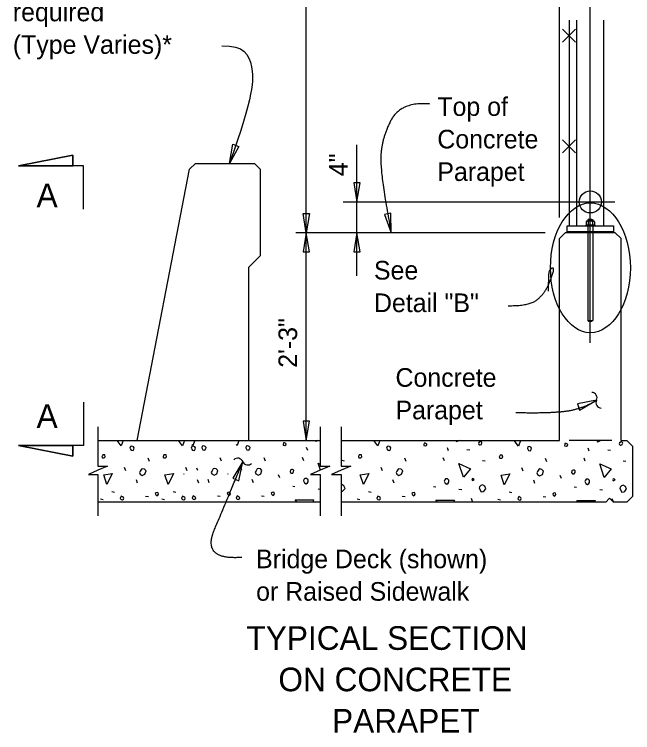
# Model space of a CAD drawing. Extents: x 0.2 to 40.8, y 0.5 to 25.7.
# Drawn here: x 33.82 to 40.51, y 11.06 to 18.84 of the extents above; entities that cross this region are included whole.
import ezdxf

# ---------------------------------------------------------------- set-up
doc = ezdxf.new("R2010")
doc.units = 0
for name, color, linetype in [('CL_Major', 7, 'Continuous'), ('Dimension', 7, 'Continuous'), ('Miscellaneous', 7, 'Continuous'), ('SteelMisc', 7, 'Continuous'), ('SteelMisc_h', 7, 'Continuous'), ('SupstrConc', 7, 'Continuous'), ('SupstrConc_h', 7, 'Continuous'), ('TextStructures', 7, 'Continuous')]:
    doc.layers.add(name, color=color, linetype=linetype)

# ---------------------------------------------------------------- blocks, each defined once
blk = doc.blocks.new('Terminator-Arrow')
at = {"layer": 'Dimension'}
blk.add_lwpolyline([(0, 0), (-0.00041, 0.000069), (-0.00041, -0.000069), (0, 0)], dxfattribs=at)
blk.add_lwpolyline([(0, 0), (-0.00041, 0.000069), (-0.00041, -0.000069)], close=True, dxfattribs=at)

msp = doc.modelspace()

# ---------------------------------------------------------------- linework, layer by layer
at = {"layer": 'CL_Major'}
for p, q in [((40.0537, 15.2829), (40.0537, 19.5023)), ((37.3776, 16.8078), (40.3194, 16.8078))]:
    msp.add_line(p, q, dxfattribs=at)
at = {"layer": 'Dimension'}
for p, q in [((36.9797, 14.2246), (36.9797, 22.8079)), ((39.7204, 16.6402), (39.7204, 19.0859)), ((37.5276, 16.0092), (37.5276, 17.4261)), ((33.8643, 17.1974), (34.4503, 17.3146)), ((34.4503, 17.3146), (34.4503, 17.1974)), ((34.5675, 17.1974), (33.8643, 17.1974)), ((34.5675, 16.7286), (34.5675, 17.1974)), ((40.0537, 16.5552), (40.0537, 16.5545)), ((39.5643, 16.4746), (36.8659, 16.4746)), ((34.5675, 14.6399), (34.5675, 14.1711)), ((34.5675, 14.1711), (33.8643, 14.1711)), ((33.8643, 14.1711), (34.4503, 14.0539)), ((34.4503, 14.0539), (34.4503, 14.1711))]:
    msp.add_line(p, q, dxfattribs=at)
for points in [[(34.4503, 17.1974), (34.4503, 17.3146), (33.8643, 17.1974)], [(37.5276, 16.8079), (37.5629, 17.0161), (37.4923, 17.0161)], [(36.9797, 16.4746), (36.9444, 16.6828), (37.015, 16.6828)], [(37.8983, 16.4746), (37.8958, 16.6858), (37.8263, 16.6731)], [(36.9797, 16.4746), (36.9444, 16.2663), (37.015, 16.2663)], [(37.5276, 16.4746), (37.4923, 16.2663), (37.5629, 16.2663)], [(40.1214, 14.6607), (39.9139, 14.6211), (39.9386, 14.5549)], [(36.9797, 14.2246), (37.015, 14.4328), (36.9444, 14.4328)], [(34.4503, 14.1711), (34.4503, 14.0539), (33.8643, 14.1711)], [(36.2916, 13.9969), (36.1831, 13.8157), (36.2488, 13.79)]]:
    msp.add_lwpolyline(points, close=True, dxfattribs=at)
for points in [[(34.7238, 14.3746), (34.7238, 13.9474), (34.8272, 13.9474), (34.7238, 13.9024), (34.6205, 13.8574), (34.7238, 13.8574), (34.7238, 13.4079)], [(37.1296, 14.3746), (37.1296, 13.9474), (37.233, 13.9474), (37.1296, 13.9024), (37.0263, 13.8574), (37.1296, 13.8574), (37.1296, 13.4079)], [(37.3569, 14.3746), (37.3569, 13.9474), (37.4602, 13.9474), (37.3569, 13.9024), (37.2536, 13.8574), (37.3569, 13.8574), (37.3569, 13.4079)]]:
    msp.add_lwpolyline(points, dxfattribs=at)
for centre, start, end in [((40.0672, 14.6869), 334.61622, 86.34344), ((40.1749, 14.6358), 154.61622, 266.34344), ((36.236, 13.9739), 22.88008, 134.6073), ((36.3458, 14.0202), 202.88008, 314.6073)]:
    msp.add_arc(centre, 0.0596, start, end, dxfattribs=at)
msp.add_ellipse((40.055, 16.0943), major_axis=(0, 0.7024), ratio=0.61552, dxfattribs=at)
for points, degree in [([(36.0647, 18.496), (36.3065, 18.5019), (36.4127, 18.3129), (36.4127, 17.9586), (36.1473, 17.2245)], 3), ([(38.3183, 17.8669), (38.0045, 17.8975), (37.7862, 17.4818), (37.7862, 17.0625), (37.8983, 16.4745)], 2), ([(39.1649, 15.6846), (39.3915, 15.6806), (39.562, 15.8155), (39.6571, 16.0457), (39.6571, 16.0974), (39.6199, 16.0825), (39.5976, 16.0298), (39.599, 15.843)], 2), ([(39.246, 14.5284), (39.5846, 14.5201), (39.9562, 14.5615), (40.1214, 14.6607)], 2), ([(36.2826, 12.9596), (36.0506, 12.9429), (35.9147, 13.1019), (36.0652, 13.445), (36.2916, 13.9969)], 2)]:
    msp.add_open_spline(points, degree=degree, dxfattribs=at)
at = {"layer": 'Miscellaneous'}
for p, q in [((39.8952, 18.6785), (39.7538, 18.5373)), ((39.7538, 18.6785), (39.8952, 18.5373)), ((39.8952, 17.4785), (39.7538, 17.3373)), ((39.7538, 17.4785), (39.8952, 17.3373)), ((40.0425, 16.6169), (40.0633, 16.6169)), ((40.0425, 16.6072), (40.0633, 16.6072)), ((39.8037, 16.4815), (40.3037, 16.4815)), ((39.8037, 16.478), (40.3037, 16.478)), ((35.3909, 14.2246), (35.3923, 14.2243)), ((38.169, 14.2246), (38.1703, 14.2243)), ((39.6751, 14.2246), (39.6941, 14.2207)), ((36.9947, 14.1164), (36.9824, 14.15)), ((38.5186, 14.1129), (38.5062, 14.1465)), ((38.7183, 14.1288), (38.7501, 14.1253)), ((40.0424, 14.1094), (40.03, 14.143)), ((40.2421, 14.1253), (40.274, 14.1218)), ((35.2827, 13.998), (35.2685, 14.0334)), ((36.0602, 14.0015), (36.0461, 14.0369)), ((36.5369, 14.0015), (36.5228, 14.0369)), ((36.9523, 14.0068), (36.9382, 14.0422)), ((37.3624, 14.0139), (37.3907, 14.0068)), ((38.0607, 13.998), (38.0466, 14.0334)), ((38.4761, 14.0033), (38.462, 14.0387)), ((38.8863, 14.0104), (38.9145, 14.0033)), ((39.5845, 13.9945), (39.5704, 14.0298)), ((39.9999, 13.9998), (39.9858, 14.0351)), ((40.4101, 14.0068), (40.4384, 13.9998)), ((35.0263, 13.8972), (35.0122, 13.9326)), ((35.6898, 13.8972), (35.6757, 13.9326)), ((35.8039, 13.9008), (35.7944, 13.9245)), ((36.2806, 13.9008), (36.2711, 13.9245)), ((37.8044, 13.8972), (37.7902, 13.9326)), ((39.3282, 13.8937), (39.3141, 13.9291)), ((36.6942, 13.8195), (36.6801, 13.8548)), ((39.7419, 13.8124), (39.7277, 13.8477)), ((35.1519, 13.7647), (35.1395, 13.7983)), ((35.8154, 13.7647), (35.803, 13.7983)), ((35.9294, 13.7682), (35.917, 13.8018)), ((36.4061, 13.7682), (36.3937, 13.8018)), ((37.9299, 13.7647), (37.9175, 13.7983)), ((39.4537, 13.7611), (39.4413, 13.7947)), ((36.8321, 13.7311), (36.8569, 13.7275)), ((37.1079, 13.7028), (37.1296, 13.699)), ((38.3559, 13.7275), (38.3807, 13.724)), ((38.6317, 13.6993), (38.6617, 13.694)), ((39.8797, 13.724), (39.9045, 13.7205)), ((40.1555, 13.6957), (40.1856, 13.6904)), ((34.8743, 13.6745), (34.9026, 13.6674)), ((35.2402, 13.6232), (35.2703, 13.6179)), ((35.5378, 13.6745), (35.5661, 13.6674)), ((36.0178, 13.6268), (36.0478, 13.6215)), ((36.4945, 13.6268), (36.5245, 13.6215)), ((37.6524, 13.6745), (37.6806, 13.6674)), ((38.0183, 13.6232), (38.0483, 13.6179)), ((39.1762, 13.671), (39.2045, 13.6639)), ((39.5421, 13.6197), (39.5721, 13.6144)), ((34.7523, 13.595), (34.7806, 13.5879)), ((35.4158, 13.595), (35.4441, 13.5879)), ((37.5304, 13.595), (37.5587, 13.5879)), ((38.7802, 13.5649), (38.7678, 13.5985)), ((39.0542, 13.5914), (39.0825, 13.5844)), ((40.304, 13.5614), (40.2916, 13.595))]:
    msp.add_line(p, q, dxfattribs=at)
for points in [[(39.8246, 18.7753), (39.8246, 16.5475)], [(34.9751, 14.1677), (34.9319, 14.2246)], [(34.9963, 14.2246), (34.9751, 14.1677)], [(35.0741, 14.1359), (35.0829, 14.12), (35.1041, 14.1164), (35.113, 14.1324), (35.1165, 14.1465), (35.1077, 14.1553), (35.0918, 14.1642), (35.0758, 14.1589), (35.0705, 14.143), (35.0741, 14.1359)], [(35.6386, 14.1677), (35.5954, 14.2246)], [(35.6598, 14.2246), (35.6386, 14.1677)], [(35.7376, 14.1359), (35.7464, 14.12), (35.7676, 14.1164), (35.7765, 14.1324), (35.78, 14.1465), (35.7712, 14.1553), (35.7553, 14.1642), (35.7393, 14.1589), (35.734, 14.143), (35.7376, 14.1359)], [(35.7526, 14.1713), (35.7438, 14.1829)], [(35.7725, 14.2246), (35.7526, 14.1713)], [(35.8516, 14.1394), (35.8605, 14.1235), (35.8817, 14.12), (35.8905, 14.1359), (35.894, 14.15), (35.8852, 14.1589), (35.8693, 14.1677), (35.8534, 14.1624), (35.8481, 14.1465), (35.8516, 14.1394)], [(36.2293, 14.1713), (36.2205, 14.1829)], [(36.2492, 14.2246), (36.2293, 14.1713)], [(36.3283, 14.1394), (36.3371, 14.1235), (36.3584, 14.12), (36.3672, 14.1359), (36.3707, 14.15), (36.3619, 14.1589), (36.346, 14.1677), (36.3301, 14.1624), (36.3248, 14.1465), (36.3283, 14.1394)], [(36.7278, 14.1748), (36.7473, 14.1695), (36.7596, 14.1783), (36.7614, 14.1907), (36.7579, 14.1942), (36.7437, 14.2013), (36.7314, 14.1995), (36.7296, 14.1872), (36.7278, 14.1748)], [(37.0831, 14.2154), (37.0859, 14.2246)], [(37.1034, 14.2246), (37.0831, 14.2154)], [(37.3569, 14.2024), (37.3571, 14.2031), (37.3569, 14.2043)], [(37.7531, 14.1677), (37.7099, 14.2246)], [(37.7744, 14.2246), (37.7531, 14.1677)], [(37.8521, 14.1359), (37.861, 14.12), (37.8822, 14.1164), (37.891, 14.1324), (37.8945, 14.1465), (37.8857, 14.1553), (37.8698, 14.1642), (37.8539, 14.1589), (37.8486, 14.143), (37.8521, 14.1359)], [(38.2516, 14.1713), (38.2711, 14.1659), (38.2834, 14.1748), (38.2852, 14.1872), (38.2817, 14.1907), (38.2675, 14.1978), (38.2552, 14.196), (38.2534, 14.1836), (38.2516, 14.1713)], [(38.6069, 14.2119), (38.6108, 14.2246)], [(38.6351, 14.2246), (38.6069, 14.2119)], [(38.8544, 14.1766), (38.8615, 14.1766), (38.8756, 14.1836), (38.881, 14.1995), (38.8792, 14.2084), (38.865, 14.2154), (38.8474, 14.2048), (38.8438, 14.1942), (38.8474, 14.1836), (38.8544, 14.1766)], [(39.2769, 14.1642), (39.231, 14.2246)], [(39.2995, 14.2246), (39.2769, 14.1642)], [(39.3759, 14.1324), (39.3848, 14.1164), (39.406, 14.1129), (39.4148, 14.1288), (39.4184, 14.143), (39.4095, 14.1518), (39.3936, 14.1606), (39.3777, 14.1553), (39.3724, 14.1394), (39.3759, 14.1324)], [(39.7754, 14.1677), (39.7949, 14.1624), (39.8073, 14.1713), (39.809, 14.1836), (39.8055, 14.1872), (39.7914, 14.1942), (39.779, 14.1925), (39.7772, 14.1801), (39.7754, 14.1677)], [(40.1308, 14.2084), (40.1357, 14.2246)], [(40.1668, 14.2246), (40.1308, 14.2084)], [(40.3782, 14.173), (40.3853, 14.173), (40.3995, 14.1801), (40.4048, 14.196), (40.403, 14.2048), (40.3889, 14.2119), (40.3712, 14.2013), (40.3676, 14.1907), (40.3712, 14.1801), (40.3782, 14.173)], [(34.7718, 14.0387), (34.793, 14.0387), (34.8036, 14.0493), (34.7983, 14.0687), (34.7753, 14.0705), (34.7718, 14.0599), (34.7665, 14.051), (34.7718, 14.0387), (34.7683, 14.0422)], [(35.4353, 14.0387), (35.4565, 14.0387), (35.4671, 14.0493), (35.4618, 14.0687), (35.4388, 14.0705), (35.4353, 14.0599), (35.43, 14.051), (35.4353, 14.0387), (35.4318, 14.0422)], [(37.5498, 14.0387), (37.571, 14.0387), (37.5816, 14.0493), (37.5763, 14.0687), (37.5534, 14.0705), (37.5498, 14.0599), (37.5445, 14.051), (37.5498, 14.0387), (37.5463, 14.0422)], [(39.0736, 14.0351), (39.0949, 14.0351), (39.1055, 14.0457), (39.1002, 14.0652), (39.0772, 14.067), (39.0736, 14.0563), (39.0683, 14.0475), (39.0736, 14.0351), (39.0701, 14.0387)], [(35.1801, 13.8601), (35.2031, 13.8477), (35.2332, 13.8601), (35.2455, 13.8972), (35.2279, 13.9149), (35.2049, 13.9202), (35.1943, 13.9132), (35.1819, 13.8937), (35.1731, 13.8778), (35.1801, 13.8601)], [(35.9577, 13.8637), (35.9807, 13.8513), (36.0107, 13.8637), (36.0231, 13.9008), (36.0054, 13.9185), (35.9824, 13.9238), (35.9718, 13.9167), (35.9594, 13.8972), (35.9506, 13.8813), (35.9577, 13.8637)], [(36.4344, 13.8637), (36.4573, 13.8513), (36.4874, 13.8637), (36.4998, 13.9008), (36.4821, 13.9185), (36.4591, 13.9238), (36.4485, 13.9167), (36.4361, 13.8972), (36.4273, 13.8813), (36.4344, 13.8637)], [(37.1323, 13.9036), (37.1079, 13.9786), (37.1296, 13.9691)], [(37.1792, 13.9474), (37.206, 13.9357)], [(37.9582, 13.8601), (37.9812, 13.8477), (38.0112, 13.8601), (38.0236, 13.8972), (38.0059, 13.9149), (37.9829, 13.9202), (37.9723, 13.9132), (37.9599, 13.8937), (37.9511, 13.8778), (37.9582, 13.8601)], [(38.6794, 13.8283), (38.6317, 13.975), (38.7572, 13.9202), (38.6794, 13.8283)], [(40.2032, 13.8248), (40.1555, 13.9715), (40.281, 13.9167), (40.2032, 13.8248)], [(34.8195, 13.7505), (34.7859, 13.8548), (34.8796, 13.8672), (34.8195, 13.7505)], [(35.483, 13.7505), (35.4494, 13.8548), (35.5431, 13.8672), (35.483, 13.7505)], [(35.6532, 13.863), (35.6503, 13.8574)], [(36.1298, 13.863), (36.127, 13.8574)], [(36.8038, 13.8866), (36.8127, 13.8707), (36.8321, 13.8725), (36.841, 13.8849), (36.8427, 13.9043), (36.8303, 13.9096), (36.8215, 13.9114), (36.8109, 13.9079), (36.8074, 13.9043), (36.8038, 13.8866)], [(37.5976, 13.7505), (37.564, 13.8548), (37.6577, 13.8672), (37.5976, 13.7505)], [(39.1214, 13.747), (39.0878, 13.8513), (39.1815, 13.8637), (39.1214, 13.747)], [(39.482, 13.8566), (39.505, 13.8442), (39.535, 13.8566), (39.5474, 13.8937), (39.5297, 13.9114), (39.5067, 13.9167), (39.4961, 13.9096), (39.4838, 13.8902), (39.4749, 13.8743), (39.482, 13.8566)], [(39.8515, 13.8796), (39.8603, 13.8637), (39.8797, 13.8654), (39.8886, 13.8778), (39.8903, 13.8972), (39.878, 13.9025), (39.8691, 13.9043), (39.8585, 13.9008), (39.855, 13.8972), (39.8515, 13.8796)], [(36.9488, 13.7876), (36.9594, 13.7664), (36.9771, 13.7558), (36.9912, 13.7664), (36.9983, 13.777), (36.9983, 13.7983), (36.9824, 13.8142), (36.9629, 13.8124), (36.9541, 13.8036), (36.9488, 13.7876)], [(38.4726, 13.7841), (38.4832, 13.7629), (38.5009, 13.7523), (38.515, 13.7629), (38.5221, 13.7735), (38.5221, 13.7947), (38.5062, 13.8106), (38.4867, 13.8089), (38.4779, 13.8), (38.4726, 13.7841)], [(38.7784, 13.7929), (38.7979, 13.8018), (38.7908, 13.8089), (38.7784, 13.8142), (38.7731, 13.8018), (38.7784, 13.7929)], [(39.9964, 13.7806), (40.007, 13.7594), (40.0247, 13.7488), (40.0388, 13.7594), (40.0459, 13.77), (40.0459, 13.7912), (40.03, 13.8071), (40.0106, 13.8053), (40.0017, 13.7965), (39.9964, 13.7806)], [(40.3022, 13.7894), (40.3217, 13.7983), (40.3146, 13.8053), (40.3022, 13.8106), (40.2969, 13.7983), (40.3022, 13.7894)], [(37.3569, 13.6752), (37.3713, 13.6763), (37.3801, 13.6851), (37.3996, 13.7046), (37.3872, 13.7346), (37.3624, 13.7488), (37.3569, 13.7465)], [(38.8491, 13.7081), (38.8721, 13.671), (38.8951, 13.6727), (38.9039, 13.6816), (38.9234, 13.701), (38.911, 13.7311), (38.8863, 13.7452), (38.8686, 13.7381), (38.8544, 13.724), (38.8491, 13.7081)], [(40.3729, 13.7046), (40.3959, 13.6674), (40.4189, 13.6692), (40.4277, 13.678), (40.4472, 13.6975), (40.4348, 13.7275), (40.4101, 13.7417), (40.3924, 13.7346), (40.3782, 13.7205), (40.3729, 13.7046)], [(34.9768, 13.5861), (34.9892, 13.5844), (35.0016, 13.5897), (35.0051, 13.6003), (34.9998, 13.6091), (34.9892, 13.6162), (34.9768, 13.6215), (34.9698, 13.6073), (34.9662, 13.5967), (34.9768, 13.5861)], [(35.3516, 13.6356), (35.3622, 13.625), (35.3728, 13.6321), (35.3799, 13.6427), (35.3764, 13.6604), (35.3675, 13.6621), (35.3551, 13.6604), (35.3445, 13.6498), (35.3516, 13.6356)], [(35.6403, 13.5861), (35.6527, 13.5844), (35.6651, 13.5897), (35.6686, 13.6003), (35.6633, 13.6091), (35.6527, 13.6162), (35.6403, 13.6215), (35.6333, 13.6073), (35.6297, 13.5967), (35.6403, 13.5861)], [(35.7544, 13.5897), (35.7668, 13.5879), (35.7791, 13.5932), (35.7827, 13.6038), (35.7774, 13.6126), (35.7668, 13.6197), (35.7544, 13.625), (35.7473, 13.6109), (35.7438, 13.6003)], [(36.1292, 13.6392), (36.1398, 13.6285), (36.1504, 13.6356), (36.1574, 13.6462), (36.1539, 13.6639), (36.1451, 13.6657), (36.1327, 13.6639), (36.1221, 13.6533), (36.1292, 13.6392)], [(36.2311, 13.5897), (36.2434, 13.5879), (36.2558, 13.5932), (36.2594, 13.6038), (36.2541, 13.6126), (36.2434, 13.6197), (36.2311, 13.625), (36.224, 13.6109), (36.2205, 13.6003)], [(36.6058, 13.6392), (36.6164, 13.6285), (36.6271, 13.6356), (36.6341, 13.6462), (36.6306, 13.6639), (36.6218, 13.6657), (36.6094, 13.6639), (36.5988, 13.6533), (36.6058, 13.6392)], [(37.7549, 13.5861), (37.7673, 13.5844), (37.7796, 13.5897), (37.7832, 13.6003), (37.7779, 13.6091), (37.7673, 13.6162), (37.7549, 13.6215), (37.7478, 13.6073), (37.7443, 13.5967), (37.7549, 13.5861)], [(38.1297, 13.6356), (38.1403, 13.625), (38.1509, 13.6321), (38.1579, 13.6427), (38.1544, 13.6604), (38.1456, 13.6621), (38.1332, 13.6604), (38.1226, 13.6498), (38.1297, 13.6356)], [(39.2787, 13.5826), (39.2911, 13.5808), (39.3034, 13.5861), (39.307, 13.5967), (39.3017, 13.6056), (39.2911, 13.6126), (39.2787, 13.6179), (39.2716, 13.6038), (39.2681, 13.5932), (39.2787, 13.5826)], [(39.6535, 13.6321), (39.6641, 13.6215), (39.6747, 13.6285), (39.6817, 13.6392), (39.6782, 13.6568), (39.6694, 13.6586), (39.657, 13.6568), (39.6464, 13.6462), (39.6535, 13.6321)], [(35.7438, 13.6003), (35.7544, 13.5897)], [(36.2205, 13.6003), (36.2311, 13.5897)], [(36.8788, 13.5578), (36.8586, 13.5844), (37.0584, 13.5826), (37.0491, 13.5578)], [(38.3999, 13.5578), (38.3824, 13.5808), (38.5822, 13.579), (38.5743, 13.5578)], [(39.921, 13.5578), (39.9063, 13.5773), (40.106, 13.5755), (40.0994, 13.5578)]]:
    msp.add_lwpolyline(points, dxfattribs=at)
msp.add_lwpolyline([(39.8037, 16.485), (40.3037, 16.485), (40.3037, 16.4745), (39.8037, 16.4745)], close=True, dxfattribs=at)
at = {"layer": 'SteelMisc'}
for p, q in [((39.9079, 16.5475), (39.9079, 18.7753)), ((40.1996, 16.5475), (40.1996, 18.7753)), ((40.0083, 16.5921), (40.0083, 16.5545)), ((40.0878, 16.6008), (40.0197, 16.6008)), ((40.0376, 16.6218), (40.028, 16.6121)), ((40.028, 16.6121), (40.028, 16.6008)), ((40.028, 16.6121), (40.0795, 16.6121)), ((40.031, 16.5924), (40.031, 16.5545)), ((40.0376, 16.6218), (40.0682, 16.6218)), ((40.0682, 16.6218), (40.0795, 16.6121)), ((40.0764, 16.5924), (40.0764, 16.5545)), ((40.0795, 16.6121), (40.0795, 16.6008)), ((40.0991, 16.5921), (40.0991, 16.5545)), ((39.9339, 16.485), (40.1735, 16.485)), ((40.0041, 16.5545), (40.0041, 16.5474)), ((40.0041, 16.5545), (40.1035, 16.5545)), ((40.0991, 16.5545), (40.0083, 16.5545)), ((40.1035, 16.5545), (40.1035, 16.5474))]:
    msp.add_line(p, q, dxfattribs=at)
msp.add_lwpolyline([(39.8037, 16.5475), (40.3037, 16.5475), (40.3037, 16.485), (39.8037, 16.485)], close=True, dxfattribs=at)
msp.add_circle((40.0537, 16.8078), 0.1198, dxfattribs=at)
for centre, radius, start, end in [((40.0197, 16.589), 0.0118, 16.59863, 164.70054), ((40.0537, 16.5661), 0.0347, 49.20147, 130.79853), ((40.0877, 16.5891), 0.0118, 15.15064, 163.50417)]:
    msp.add_arc(centre, radius, start, end, dxfattribs=at)
at = {"layer": 'SteelMisc_h'}
for p, q in [((40.0277, 16.5475), (40.0277, 15.5243)), ((40.0798, 16.5475), (40.0798, 15.5243)), ((40.0277, 15.5243), (40.0798, 15.5243)), ((40.0277, 15.5243), (40.0359, 15.5162)), ((40.0359, 15.5162), (40.0716, 15.5162)), ((40.0798, 15.5243), (40.0716, 15.5162))]:
    msp.add_line(p, q, dxfattribs=at)
at = {"layer": 'SupstrConc'}
for p, q in [((39.7829, 16.4745), (39.7204, 16.4112)), ((39.7204, 14.2246), (39.7204, 16.4112)), ((40.3245, 16.4745), (39.7829, 16.4745)), ((40.3245, 16.4745), (39.7829, 16.4745)), ((40.3245, 16.4745), (40.3871, 16.4112)), ((40.3871, 14.2246), (40.3871, 16.4112)), ((34.7238, 14.2246), (37.1296, 14.2246)), ((37.3569, 14.2246), (39.7204, 14.2246)), ((40.3871, 14.2246), (40.4496, 14.2246)), ((40.4496, 14.2246), (40.5121, 14.1621)), ((40.5121, 14.1621), (40.5121, 13.6204)), ((40.5121, 13.6204), (40.4496, 13.5579)), ((40.2204, 13.5579), (37.3569, 13.5579)), ((40.2204, 13.5579), (40.2621, 13.5995)), ((40.2621, 13.5995), (40.3037, 13.5579)), ((40.4496, 13.5579), (40.3037, 13.5579))]:
    msp.add_line(p, q, dxfattribs=at)
at = {"layer": 'SupstrConc_h'}
for p, q in [((35.7163, 17.162), (35.7788, 17.2245)), ((35.7788, 17.2245), (36.4178, 17.2246)), ((36.4178, 17.2245), (36.4803, 17.162)), ((35.147, 14.2246), (35.7163, 17.162)), ((36.4803, 17.162), (36.4803, 16.2245)), ((36.4803, 16.2245), (36.3553, 16.0995)), ((36.3553, 16.0995), (36.3553, 14.2246)), ((40.2885, 14.2246), (39.8234, 14.2246)), ((37.1296, 13.5579), (34.7238, 13.5579))]:
    msp.add_line(p, q, dxfattribs=at)

# ---------------------------------------------------------------- block references
at = {"layer": 'Dimension', "xscale": 507.9999699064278, "yscale": -507.99996990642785, "rotation": -109.44616743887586}
msp.add_blockref('Terminator-Arrow', (36.1473, 17.2245), dxfattribs=at)

# ---------------------------------------------------------------- texts
at = {"layer": 'Dimension'}
for s, height, p in [('required', 0.2016, (33.8024, 18.763)), ('(Type Varies)*', 0.2016, (33.8024, 18.411)), ('Top of ', 0.2016, (38.3979, 17.7388)), ('Concrete', 0.2016, (38.3979, 17.3868)), ('Parapet', 0.2016, (38.3979, 17.0348)), ('See ', 0.2016, (37.7119, 15.9673)), ('Detail "B"', 0.2016, (37.7119, 15.6153)), ('Concrete', 0.2016, (37.9448, 14.8065)), ('Parapet', 0.2016, (37.9448, 14.4545)), ('Bridge Deck (shown)', 0.2016, (36.4361, 12.8428)), ('or Raised Sidewalk', 0.2016, (36.4361, 12.4908)), ('TYPICAL SECTION', 0.256001, (36.3315, 11.9589)), ('ON CONCRETE', 0.256001, (36.6769, 11.5109)), ('PARAPET', 0.256, (37.2584, 11.0629))]:
    msp.add_text(s, height=height, dxfattribs=at).set_placement(p)
at = {"layer": 'TextStructures'}
for s, p in [('4"', (37.4279, 17.0864)), ('2\'-3"', (36.8797, 15.0126))]:
    msp.add_text(s, height=0.2016, rotation=90, dxfattribs=at).set_placement(p)
for p in [(34.0596, 16.7507), (34.0596, 14.362)]:
    msp.add_text('A', height=0.256, dxfattribs=at).set_placement(p)

doc.saveas('drawing.dxf')
